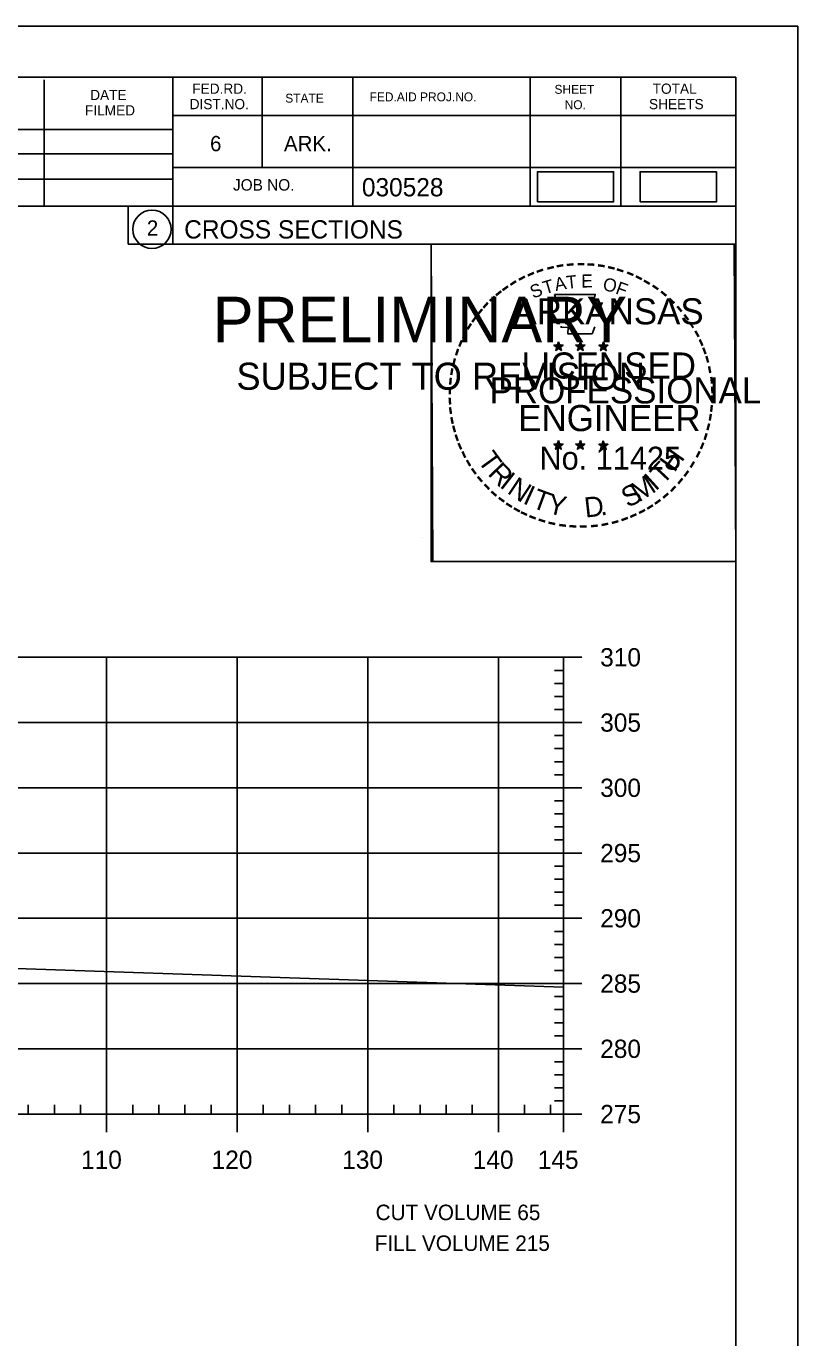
# Model space of a CAD drawing. Extents: x 1370843 to 1371177, y 380307 to 382654.
# Drawn here: x 1371117.6 to 1371176.6, y 382127 to 382227.5 of the extents above; entities that cross this region are included whole.
import ezdxf

# ---------------------------------------------------------------- set-up
doc = ezdxf.new("R2010")
doc.units = 0
for name, color, linetype in [('R_Axis', 7, 'Continuous'), ('R_Axis Annot', 7, 'Continuous'), ('R_Border', 7, 'Continuous'), ('R_Border Notes', 7, 'Continuous'), ('R_Border PE', 7, 'Continuous'), ('R_Border Prem', 7, 'Continuous'), ('R_Draft', 7, 'Continuous'), ('R_Exist Surface', 7, 'Continuous'), ('R_Grid', 7, 'Continuous'), ('R_No Plot', 7, 'Continuous')]:
    doc.layers.add(name, color=color, linetype=linetype)

msp = doc.modelspace()

# ---------------------------------------------------------------- linework, layer by layer
at = {"layer": 'R_Axis'}
for p, q in [((1371158.71, 382144.15), (1371158.71, 382179.15)), ((1371160.11, 382179.15), (1371158.71, 382179.15)), ((1371158.71, 382178.15), (1371158.01, 382178.15)), ((1371158.71, 382177.15), (1371158.01, 382177.15)), ((1371158.71, 382176.15), (1371158.01, 382176.15)), ((1371158.71, 382175.15), (1371158.01, 382175.15)), ((1371160.11, 382174.15), (1371158.71, 382174.15)), ((1371158.71, 382173.15), (1371158.01, 382173.15)), ((1371158.71, 382172.15), (1371158.01, 382172.15)), ((1371158.71, 382171.15), (1371158.01, 382171.15)), ((1371158.71, 382170.15), (1371158.01, 382170.15)), ((1371160.11, 382169.15), (1371158.71, 382169.15)), ((1371158.71, 382168.15), (1371158.01, 382168.15)), ((1371158.71, 382167.15), (1371158.01, 382167.15)), ((1371158.71, 382166.15), (1371158.01, 382166.15)), ((1371158.71, 382165.15), (1371158.01, 382165.15)), ((1371160.11, 382164.15), (1371158.71, 382164.15)), ((1371158.71, 382163.15), (1371158.01, 382163.15)), ((1371158.71, 382162.15), (1371158.01, 382162.15)), ((1371158.71, 382161.15), (1371158.01, 382161.15)), ((1371158.71, 382160.15), (1371158.01, 382160.15)), ((1371160.11, 382159.15), (1371158.71, 382159.15)), ((1371158.71, 382158.15), (1371158.01, 382158.15)), ((1371158.71, 382157.15), (1371158.01, 382157.15)), ((1371158.71, 382156.15), (1371158.01, 382156.15)), ((1371158.71, 382155.15), (1371158.01, 382155.15)), ((1371160.11, 382154.15), (1371158.71, 382154.15)), ((1371158.71, 382153.15), (1371158.01, 382153.15)), ((1371158.71, 382152.15), (1371158.01, 382152.15)), ((1371158.71, 382151.15), (1371158.01, 382151.15)), ((1371158.71, 382150.15), (1371158.01, 382150.15)), ((1371160.11, 382149.15), (1371158.71, 382149.15)), ((1371158.71, 382148.15), (1371158.01, 382148.15)), ((1371158.71, 382147.15), (1371158.01, 382147.15)), ((1371158.71, 382146.15), (1371158.01, 382146.15)), ((1371117.71, 382144.15), (1371117.71, 382144.85)), ((1371119.71, 382144.15), (1371119.71, 382144.85)), ((1371121.71, 382144.15), (1371121.71, 382144.85)), ((1371125.71, 382144.15), (1371125.71, 382144.85)), ((1371127.71, 382144.15), (1371127.71, 382144.85)), ((1371129.71, 382144.15), (1371129.71, 382144.85)), ((1371131.71, 382144.15), (1371131.71, 382144.85)), ((1371135.71, 382144.15), (1371135.71, 382144.85)), ((1371137.71, 382144.15), (1371137.71, 382144.85)), ((1371139.71, 382144.15), (1371139.71, 382144.85)), ((1371141.71, 382144.15), (1371141.71, 382144.85)), ((1371145.71, 382144.15), (1371145.71, 382144.85)), ((1371147.71, 382144.15), (1371147.71, 382144.85)), ((1371149.71, 382144.15), (1371149.71, 382144.85)), ((1371151.71, 382144.15), (1371151.71, 382144.85)), ((1371155.71, 382144.15), (1371155.71, 382144.85)), ((1371157.71, 382144.15), (1371157.71, 382144.85)), ((1371158.71, 382145.15), (1371158.01, 382145.15)), ((1370868.71, 382144.15), (1371158.71, 382144.15)), ((1371123.71, 382142.75), (1371123.71, 382144.15)), ((1371133.71, 382142.75), (1371133.71, 382144.15)), ((1371143.71, 382142.75), (1371143.71, 382144.15)), ((1371153.71, 382142.75), (1371153.71, 382144.15)), ((1371158.71, 382142.75), (1371158.71, 382144.15)), ((1371160.11, 382144.15), (1371158.71, 382144.15))]:
    msp.add_line(p, q, dxfattribs=at)
at = {"layer": 'R_Border'}
for p, q in [((1370855.71, 382223.61), (1371171.89, 382223.61)), ((1371118.93, 382213.73), (1371118.93, 382223.41)), ((1371128.79, 382223.61), (1371128.79, 382210.81)), ((1371135.63, 382223.61), (1371135.63, 382216.67)), ((1371142.57, 382223.61), (1371142.57, 382213.73)), ((1371156.15, 382223.61), (1371156.15, 382213.73)), ((1371163.09, 382223.61), (1371163.09, 382213.73)), ((1371171.89, 382018.15), (1371171.89, 382223.61)), ((1371171.89, 382220.67), (1371128.79, 382220.67)), ((1371171.89, 382220.69), (1371171.89, 382220.69)), ((1371089.63, 382219.59), (1371128.79, 382219.59)), ((1371089.63, 382217.73), (1371128.79, 382217.73)), ((1371171.89, 382216.67), (1371128.79, 382216.67)), ((1371131.75, 382216.67), (1371171.89, 382216.67)), ((1371089.63, 382215.79), (1371128.79, 382215.79)), ((1371171.89, 382213.73), (1371089.63, 382213.73)), ((1371128.79, 382210.81), (1371171.89, 382210.81))]:
    msp.add_line(p, q, dxfattribs=at)
msp.add_circle((1371127.18, 382211.95), 1.47, dxfattribs=at)
at = {"layer": 'R_Border PE'}
for p, q in [((1371158.32, 382203.32), (1371158.28, 382203.07)), ((1371158.32, 382202.96), (1371158.32, 382203.32)), ((1371158.32, 382203.32), (1371158.37, 382203.07)), ((1371159.99, 382203.32), (1371159.95, 382203.07)), ((1371159.99, 382202.96), (1371159.99, 382203.32)), ((1371159.99, 382203.32), (1371160.04, 382203.07)), ((1371161.76, 382203.31), (1371161.72, 382203.06)), ((1371161.76, 382202.94), (1371161.76, 382203.31)), ((1371161.76, 382203.31), (1371161.81, 382203.06)), ((1371157.97, 382203.07), (1371158.32, 382202.96)), ((1371157.97, 382203.07), (1371158.23, 382203.02)), ((1371157.97, 382203.07), (1371158.21, 382202.95)), ((1371158.11, 382202.66), (1371158.32, 382202.96)), ((1371158.11, 382202.66), (1371158.23, 382202.9)), ((1371158.11, 382202.66), (1371158.32, 382202.88)), ((1371158.67, 382203.07), (1371158.32, 382202.96)), ((1371158.54, 382202.66), (1371158.32, 382202.96)), ((1371158.54, 382202.66), (1371158.32, 382202.87)), ((1371158.67, 382203.07), (1371158.38, 382203.02)), ((1371158.54, 382202.66), (1371158.4, 382202.95)), ((1371158.67, 382203.07), (1371158.47, 382202.97)), ((1371159.64, 382203.07), (1371159.99, 382202.96)), ((1371159.64, 382203.07), (1371159.9, 382203.02)), ((1371159.64, 382203.07), (1371159.88, 382202.95)), ((1371159.78, 382202.66), (1371159.99, 382202.96)), ((1371159.78, 382202.66), (1371159.9, 382202.9)), ((1371159.78, 382202.66), (1371159.99, 382202.88)), ((1371160.34, 382203.07), (1371159.99, 382202.96)), ((1371160.21, 382202.66), (1371159.99, 382202.96)), ((1371160.21, 382202.66), (1371159.99, 382202.87)), ((1371160.34, 382203.07), (1371160.05, 382203.02)), ((1371160.21, 382202.66), (1371160.07, 382202.95)), ((1371160.34, 382203.07), (1371160.14, 382202.97)), ((1371161.41, 382203.06), (1371161.76, 382202.94)), ((1371161.41, 382203.06), (1371161.66, 382203.01)), ((1371161.41, 382203.06), (1371161.64, 382202.93)), ((1371161.54, 382202.65), (1371161.76, 382202.94)), ((1371161.54, 382202.65), (1371161.67, 382202.89)), ((1371161.54, 382202.65), (1371161.75, 382202.86)), ((1371161.97, 382202.65), (1371161.75, 382202.86)), ((1371162.1, 382203.06), (1371161.76, 382202.94)), ((1371161.97, 382202.65), (1371161.76, 382202.94)), ((1371162.1, 382203.06), (1371161.82, 382203.01)), ((1371161.97, 382202.65), (1371161.83, 382202.94)), ((1371162.1, 382203.06), (1371161.9, 382202.95)), ((1371157.97, 382195.49), (1371158.32, 382195.38)), ((1371157.97, 382195.49), (1371158.22, 382195.45)), ((1371157.97, 382195.49), (1371158.21, 382195.37)), ((1371158.1, 382195.09), (1371158.32, 382195.38)), ((1371158.1, 382195.09), (1371158.23, 382195.33)), ((1371158.1, 382195.09), (1371158.32, 382195.3)), ((1371158.32, 382195.75), (1371158.28, 382195.5)), ((1371158.32, 382195.38), (1371158.32, 382195.75)), ((1371158.32, 382195.75), (1371158.37, 382195.5)), ((1371158.67, 382195.49), (1371158.32, 382195.38)), ((1371158.53, 382195.09), (1371158.32, 382195.38)), ((1371158.53, 382195.09), (1371158.32, 382195.3)), ((1371158.67, 382195.49), (1371158.38, 382195.45)), ((1371158.53, 382195.09), (1371158.39, 382195.38)), ((1371158.67, 382195.49), (1371158.46, 382195.39)), ((1371159.64, 382195.49), (1371159.99, 382195.38)), ((1371159.64, 382195.49), (1371159.89, 382195.45)), ((1371159.64, 382195.49), (1371159.88, 382195.37)), ((1371159.77, 382195.09), (1371159.99, 382195.38)), ((1371159.77, 382195.09), (1371159.9, 382195.33)), ((1371159.77, 382195.09), (1371159.99, 382195.3)), ((1371159.99, 382195.75), (1371159.95, 382195.5)), ((1371159.99, 382195.38), (1371159.99, 382195.75)), ((1371159.99, 382195.75), (1371160.04, 382195.5)), ((1371160.33, 382195.49), (1371159.99, 382195.38)), ((1371160.2, 382195.09), (1371159.99, 382195.38)), ((1371160.2, 382195.09), (1371159.99, 382195.3)), ((1371160.33, 382195.49), (1371160.05, 382195.45)), ((1371160.2, 382195.09), (1371160.06, 382195.38)), ((1371160.33, 382195.49), (1371160.13, 382195.39)), ((1371161.41, 382195.48), (1371161.75, 382195.37)), ((1371161.41, 382195.48), (1371161.66, 382195.44)), ((1371161.41, 382195.48), (1371161.64, 382195.36)), ((1371161.54, 382195.08), (1371161.75, 382195.37)), ((1371161.54, 382195.08), (1371161.66, 382195.32)), ((1371161.54, 382195.08), (1371161.75, 382195.29)), ((1371161.75, 382195.74), (1371161.71, 382195.49)), ((1371161.75, 382195.37), (1371161.75, 382195.74)), ((1371161.75, 382195.74), (1371161.8, 382195.49)), ((1371162.1, 382195.48), (1371161.75, 382195.37)), ((1371161.97, 382195.08), (1371161.75, 382195.37)), ((1371161.97, 382195.08), (1371161.75, 382195.29)), ((1371162.1, 382195.48), (1371161.82, 382195.44)), ((1371161.97, 382195.08), (1371161.83, 382195.37)), ((1371162.1, 382195.48), (1371161.9, 382195.38))]:
    msp.add_line(p, q, dxfattribs=at)
for points in [[(1371158.01, 382206.95), (1371158.28, 382206.12)], [(1371161.53, 382206.02), (1371161.67, 382206.31), (1371160.98, 382206.28), (1371161.13, 382206.95), (1371158.01, 382206.95)], [(1371158.51, 382204.52), (1371158.51, 382204.44), (1371159.07, 382204.42), (1371159.02, 382203.94), (1371160.89, 382203.94), (1371161.09, 382204.48)], [(1371158.32, 382203.32), (1371158.54, 382202.66), (1371157.97, 382203.07), (1371158.67, 382203.07), (1371158.11, 382202.66), (1371158.32, 382203.32)], [(1371159.99, 382203.32), (1371160.21, 382202.66), (1371159.64, 382203.07), (1371160.34, 382203.07), (1371159.78, 382202.66), (1371159.99, 382203.32)], [(1371161.76, 382203.31), (1371161.97, 382202.65), (1371161.41, 382203.06), (1371162.1, 382203.06), (1371161.54, 382202.65), (1371161.76, 382203.31)], [(1371158.32, 382195.75), (1371158.53, 382195.09), (1371157.97, 382195.49), (1371158.67, 382195.49), (1371158.1, 382195.09), (1371158.32, 382195.75)], [(1371159.99, 382195.75), (1371160.2, 382195.09), (1371159.64, 382195.49), (1371160.33, 382195.49), (1371159.77, 382195.09), (1371159.99, 382195.75)], [(1371161.75, 382195.74), (1371161.97, 382195.08), (1371161.41, 382195.48), (1371162.1, 382195.48), (1371161.54, 382195.08), (1371161.75, 382195.74)]]:
    msp.add_lwpolyline(points, dxfattribs=at)
for centre, radius in [((1371158.32, 382202.96), 0.172), ((1371158.32, 382202.96), 0.145), ((1371159.99, 382202.96), 0.172), ((1371159.99, 382202.96), 0.145), ((1371161.76, 382202.94), 0.172), ((1371161.76, 382202.94), 0.145), ((1371158.32, 382202.96), 0.116), ((1371158.32, 382202.96), 0.0991), ((1371158.32, 382202.96), 0.0747), ((1371158.32, 382202.96), 0.0495), ((1371158.32, 382202.96), 0.0296), ((1371159.99, 382202.96), 0.116), ((1371159.99, 382202.96), 0.0991), ((1371159.99, 382202.96), 0.0747), ((1371159.99, 382202.96), 0.0495), ((1371159.99, 382202.96), 0.0296), ((1371161.76, 382202.94), 0.116), ((1371161.76, 382202.94), 0.0991), ((1371161.76, 382202.94), 0.0747), ((1371161.76, 382202.94), 0.0495), ((1371161.76, 382202.94), 0.0296), ((1371158.32, 382195.38), 0.172), ((1371158.32, 382195.38), 0.145), ((1371158.32, 382195.38), 0.116), ((1371158.32, 382195.38), 0.0991), ((1371158.32, 382195.38), 0.0747), ((1371158.32, 382195.38), 0.0495), ((1371158.32, 382195.38), 0.0296), ((1371159.99, 382195.38), 0.172), ((1371159.99, 382195.38), 0.145), ((1371159.99, 382195.38), 0.116), ((1371159.99, 382195.38), 0.0991), ((1371159.99, 382195.38), 0.0747), ((1371159.99, 382195.38), 0.0495), ((1371159.99, 382195.38), 0.0296), ((1371161.75, 382195.37), 0.172), ((1371161.75, 382195.37), 0.145), ((1371161.75, 382195.37), 0.116), ((1371161.75, 382195.37), 0.0991), ((1371161.75, 382195.37), 0.0747), ((1371161.75, 382195.37), 0.0495), ((1371161.75, 382195.37), 0.0296)]:
    msp.add_circle(centre, radius, dxfattribs=at)
at = {"layer": 'R_Draft'}
for points in [[(1371156.7, 382214.05), (1371162.54, 382214.05), (1371162.54, 382216.36), (1371156.7, 382216.36)], [(1371164.57, 382214.05), (1371170.41, 382214.05), (1371170.41, 382216.36), (1371164.57, 382216.36)]]:
    msp.add_lwpolyline(points, close=True, dxfattribs=at)
at = {"layer": 'R_Exist Surface'}
msp.add_line((1371083.23, 382156.46), (1371158.71, 382153.86), dxfattribs=at)
at = {"layer": 'R_Grid'}
for p, q in [((1370868.71, 382179.15), (1371158.71, 382179.15)), ((1371123.71, 382144.15), (1371123.71, 382179.15)), ((1371133.71, 382144.15), (1371133.71, 382179.15)), ((1371143.71, 382144.15), (1371143.71, 382179.15)), ((1371153.71, 382144.15), (1371153.71, 382179.15)), ((1371158.71, 382144.15), (1371158.71, 382179.15)), ((1370868.71, 382174.15), (1371158.71, 382174.15)), ((1370868.71, 382169.15), (1371158.71, 382169.15)), ((1370868.71, 382164.15), (1371158.71, 382164.15)), ((1370868.71, 382159.15), (1371158.71, 382159.15)), ((1370868.71, 382154.15), (1371158.71, 382154.15)), ((1370868.71, 382149.15), (1371158.71, 382149.15)), ((1370868.71, 382144.15), (1371158.71, 382144.15))]:
    msp.add_line(p, q, dxfattribs=at)
at = {"layer": 'R_No Plot'}
for p, q in [((1370843.31, 382227.51), (1371176.64, 382227.51)), ((1371147.92, 382188.36), (1371147.92, 382188.36))]:
    msp.add_line(p, q, dxfattribs=at)
for points in [[(1370843.3, 382227.51), (1371176.64, 382227.51), (1371176.64, 382014.17), (1370843.3, 382014.17)], [(1371089.63, 382223.61), (1371089.63, 382213.73), (1371125.36, 382213.73), (1371125.36, 382210.81), (1371148.56, 382210.81), (1371148.56, 382186.48), (1371171.89, 382186.48), (1371171.89, 382018.15), (1370855.71, 382018.15), (1370855.71, 382223.61)], [(1371148.56, 382210.81), (1371171.77, 382210.81), (1371171.89, 382186.48), (1371148.68, 382186.48)]]:
    msp.add_lwpolyline(points, close=True, dxfattribs=at)

# ---------------------------------------------------------------- texts
at = {"layer": 'R_Axis Annot'}
for s, p in [('310', (1371161.51, 382178.45)), ('305', (1371161.51, 382173.45)), ('300', (1371161.51, 382168.45)), ('295', (1371161.51, 382163.45)), ('290', (1371161.51, 382158.45)), ('285', (1371161.51, 382153.45)), ('280', (1371161.51, 382148.45)), ('275', (1371161.51, 382143.45)), ('110', (1371121.75, 382139.95)), ('120', (1371131.75, 382139.95)), ('130', (1371141.75, 382139.95)), ('140', (1371151.75, 382139.95)), ('145', (1371156.73, 382139.95))]:
    msp.add_text(s, height=1.4, dxfattribs=at).set_placement(p)
at = {"layer": 'R_Border'}
for s, height, p in [('DATE', 0.782, (1371122.45, 382221.85)), ('FED.RD.', 0.782, (1371130.27, 382222.33)), ('STATE', 0.684, (1371137.39, 382221.65)), ('FED.AID PROJ.NO.', 0.684, (1371143.85, 382221.75)), ('SHEET', 0.684, (1371158.01, 382222.33)), ('TOTAL', 0.782, (1371165.53, 382222.33)), ('FILMED', 0.782, (1371122.05, 382220.67)), ('DIST.NO.', 0.782, (1371130.07, 382221.15)), ('NO.', 0.684, (1371158.79, 382221.15)), ('SHEETS', 0.782, (1371165.25, 382221.15)), ('6', 1.17, (1371131.63, 382217.93)), ('ARK.', 1.172, (1371137.29, 382217.93)), ('JOB NO.', 0.879, (1371133.39, 382214.91)), ('030528', 1.4, (1371143.26, 382214.47)), ('2', 1.17, (1371126.79, 382211.46)), ('CROSS SECTIONS', 1.4, (1371129.65, 382211.24))]:
    msp.add_text(s, height=height, rotation=360, dxfattribs=at).set_placement(p)
at = {"layer": 'R_Border Notes'}
for s, p in [('CUT VOLUME 65', (1371144.31, 382136.02)), ('FILL VOLUME 215', (1371144.24, 382133.66))]:
    msp.add_text(s, height=1.1875, dxfattribs=at).set_placement(p)
at = {"layer": 'R_Border PE'}
for s, height, rotation, p in [('-', 1.6, 13.6301, (1371157.51, 382208.31)), ('-', 1.6, 10.2193, (1371158.19, 382208.48)), ('-', 1.6, 5.8968, (1371158.92, 382208.59)), ('-', 1.6, 0.1862, (1371159.69, 382208.66)), ('-', 1.6, 357.743, (1371160.41, 382208.64)), ('-', 1.6, 352.1617, (1371161.16, 382208.59)), ('-', 1.6, 347.2049, (1371161.88, 382208.47)), ('-', 1.6, 28.7918, (1371155.5, 382207.49)), ('-', 1.6, 24.3072, (1371156.13, 382207.8)), ('-', 1.6, 19.1761, (1371156.76, 382208.07)), ('T', 1, 16.4036, (1371157.28, 382206.95)), ('A', 1, 11.2132, (1371158.11, 382207.21)), ('T', 1, 6.0228, (1371158.96, 382207.37)), ('E', 1, 0.8323, (1371160.06, 382207.48)), ('O', 1, 350.4515, (1371161.67, 382207.27)), ('-', 1.6, 342.3362, (1371162.51, 382208.32)), ('-', 1.6, 337.8551, (1371163.25, 382208.1)), ('-', 1.6, 334.1211, (1371163.88, 382207.83)), ('-', 1.6, 38.9507, (1371153.84, 382206.34)), ('-', 1.6, 36.2317, (1371154.32, 382206.72)), ('-', 1.6, 34.0636, (1371154.9, 382207.12)), ('S', 1, 21.594, (1371156.37, 382206.62)), ('F', 1, 340.0707, (1371162.62, 382207.04)), ('-', 1.6, 329.6409, (1371164.46, 382207.54)), ('-', 1.6, 325.8627, (1371165.1, 382207.18)), ('-', 1.6, 320.5297, (1371165.71, 382206.76)), ('-', 1.6, 48.423, (1371152.96, 382205.45)), ('-', 1.6, 42.9622, (1371153.41, 382205.93)), ('ARKANSAS', 2, 360, (1371154.87, 382204.66)), ('-', 1.6, 315.5786, (1371166.31, 382206.27)), ('-', 1.6, 54.2325, (1371152.15, 382204.4)), ('-', 1.6, 50.6142, (1371152.56, 382204.96)), ('-', 1.6, 309.8797, (1371166.88, 382205.72)), ('-', 1.6, 306.6522, (1371167.4, 382205.12)), ('-', 1.6, 62.8713, (1371151.51, 382203.25)), ('-', 1.6, 58.0706, (1371151.82, 382203.87)), ('-', 1.4, 303.6753, (1371167.89, 382204.55)), ('-', 1.6, 299.6684, (1371168.21, 382203.94)), ('-', 1.6, 67.7743, (1371151.25, 382202.64)), ('-', 1.6, 294.6628, (1371168.53, 382203.33)), ('-', 1.6, 72.3945, (1371151.03, 382202.01)), ('LICENSED', 2, 360, (1371155.47, 382200.51)), ('DWB', 0.01, 360, (1371158.31, 382202.95)), ('DWB', 0.01, 360, (1371159.98, 382202.95)), ('DWB', 0.01, 360, (1371161.74, 382202.94)), ('-', 1.6, 290.5728, (1371168.79, 382202.75)), ('-', 1.6, 285.1233, (1371169.02, 382202.17)), ('-', 1.6, 81.2013, (1371150.7, 382200.59)), ('-', 1.6, 75.461, (1371150.83, 382201.3)), ('-', 1.6, 280.5493, (1371169.22, 382201.43)), ('-', 1.6, 85.1863, (1371150.63, 382199.9)), ('PROFESSIONAL', 2, 360, (1371153.04, 382198.6)), ('-', 1.6, 276.5962, (1371169.39, 382200.66)), ('-', 1.6, 89.0622, (1371150.6, 382199.19)), ('-', 1.6, 274.3301, (1371169.45, 382199.94)), ('-', 1.6, 269.9407, (1371169.48, 382199.31)), ('-', 1.6, 94.1959, (1371150.64, 382198.47)), ('-', 1.6, 98.9479, (1371150.71, 382197.8)), ('ENGINEER', 2, 360, (1371155.23, 382196.48)), ('-', 1.6, 263.5172, (1371169.46, 382198.64)), ('-', 1.6, 101.7149, (1371150.84, 382197.07)), ('-', 1.6, 255.7626, (1371169.28, 382197.31)), ('-', 1.6, 260.9953, (1371169.39, 382197.99)), ('-', 1.6, 105.4578, (1371151.01, 382196.47)), ('-', 1.6, 109.0874, (1371151.22, 382195.84)), ('-', 1.6, 252.8681, (1371169.1, 382196.59)), ('-', 1.6, 114.0643, (1371151.47, 382195.25)), ('T', 1.54, 306.0406, (1371152.08, 382194.22)), ('No. 11425', 1.757, 360, (1371156.86, 382193.53)), ('DWB', 0.01, 360, (1371158.31, 382195.38)), ('DWB', 0.01, 360, (1371159.98, 382195.38)), ('DWB', 0.01, 360, (1371161.74, 382195.37)), ('H', 1.54, 54.6088, (1371167.2, 382193.26)), ('-', 1.6, 247.8887, (1371168.88, 382195.92)), ('-', 1.6, 115.7289, (1371151.78, 382194.63)), ('-', 1.6, 120.4471, (1371152.14, 382194.04)), ('R', 1.54, 314.005, (1371152.84, 382193.17)), ('T', 1.54, 46.6444, (1371166.31, 382192.31)), ('-', 1.6, 239.0712, (1371168.22, 382194.54)), ('-', 1.6, 244.6197, (1371168.61, 382195.29)), ('-', 1.6, 125.8934, (1371152.54, 382193.48)), ('-', 1.6, 130.7181, (1371153, 382192.93)), ('I', 1.54, 321.9694, (1371153.74, 382192.24)), ('M', 1.54, 32.6563, (1371164.46, 382190.99)), ('I', 1.54, 42.1136, (1371165.75, 382191.84)), ('-', 1.6, 233.8452, (1371167.82, 382193.88)), ('-', 1.6, 134.2238, (1371153.52, 382192.39)), ('N', 1.54, 326.5002, (1371154.31, 382191.77)), ('I', 1.54, 335.3603, (1371155.52, 382190.98)), ('T', 1.54, 339.8912, (1371156.18, 382190.66)), ('S', 1.54, 26.9312, (1371163.62, 382190.58)), ('-', 1.6, 225.7653, (1371166.91, 382192.75)), ('-', 1.6, 231.2538, (1371167.39, 382193.32)), ('-', 1.6, 138.9338, (1371154.04, 382191.92)), ('-', 1.6, 144.6463, (1371154.6, 382191.52)), ('Y', 1.54, 347.8556, (1371157.39, 382190.21)), ('D', 1.54, 6.3969, (1371160.38, 382189.85)), ('-', 1.6, 215.7363, (1371165.84, 382191.77)), ('-', 1.6, 221.0851, (1371166.39, 382192.24)), ('-', 1.6, 148.0898, (1371155.16, 382191.14)), ('-', 1.6, 151.5704, (1371155.74, 382190.82)), ('-', 1.6, 154.6002, (1371156.26, 382190.57)), ('-', 1.6, 158.5612, (1371156.89, 382190.32)), ('.', 1.54, 13.7642, (1371161.57, 382189.98)), ('-', 1.6, 204.2516, (1371164.12, 382190.72)), ('-', 1.6, 207.3568, (1371164.75, 382191.04)), ('-', 1.6, 212.2491, (1371165.3, 382191.38)), ('-', 1.6, 162.7983, (1371157.57, 382190.11)), ('-', 1.6, 167.5555, (1371158.29, 382189.94)), ('-', 1.6, 173.1155, (1371159.06, 382189.83)), ('-', 1.6, 176.5183, (1371159.81, 382189.78)), ('-', 1.6, 181.5918, (1371160.55, 382189.8)), ('-', 1.6, 185.8167, (1371161.36, 382189.87)), ('-', 1.6, 191.2858, (1371162.1, 382190.01)), ('-', 1.6, 195.4743, (1371162.83, 382190.2)), ('-', 1.6, 200.7184, (1371163.5, 382190.45))]:
    msp.add_text(s, height=height, rotation=rotation, dxfattribs=at).set_placement(p)
at = {"layer": 'R_Border Prem'}
for s, height, p in [('PRELIMINARY', 3.5, (1371131.84, 382203.28)), ('DWB', 0.01, (1371132.59, 382205.12)), ('SUBJECT TO REVISION', 2.0751, (1371133.65, 382199.65))]:
    msp.add_text(s, height=height, rotation=360, dxfattribs=at).set_placement(p)

doc.saveas('drawing.dxf')
